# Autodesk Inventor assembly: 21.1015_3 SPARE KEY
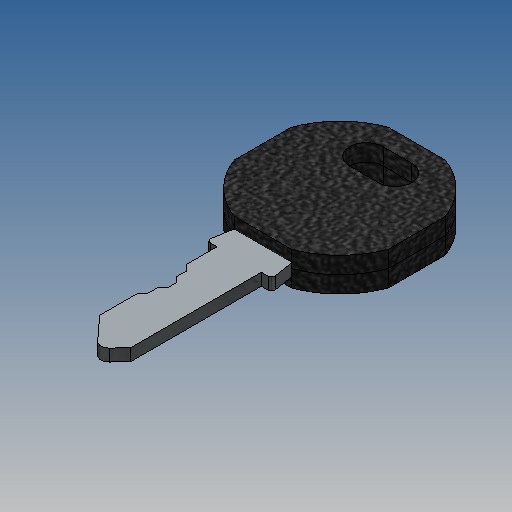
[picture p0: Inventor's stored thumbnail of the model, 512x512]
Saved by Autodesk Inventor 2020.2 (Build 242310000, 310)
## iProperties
Created: 2007-03
Part Number: 21.1015_3 SPARE KEY
Document SubType Name: Assembly
Designer: Andy Moles
Mass: 2.63365 g
Surface Area: 28.5344 cm^2
Volume: 2.50968 cm^3
Density: 1.0494 g/cm^3
Author: Andy Moles
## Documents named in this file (3)
- Y:\INVENTOR LIBRARIES\PARTS LIBRARY\HANDLES LOCKS STOPS\21.1015_3 SPARE KEY.iam
- Y:\INVENTOR LIBRARIES\PARTS LIBRARY\HANDLES LOCKS STOPS\SUBCOMPONENTS\EMKA SUBCOMPONENTS\1108-14-333_PRT.ipt
- Y:\INVENTOR LIBRARIES\PARTS LIBRARY\HANDLES LOCKS STOPS\SUBCOMPONENTS\EMKA SUBCOMPONENTS\1108-15-01_PRT.ipt
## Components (3 placed, 3 different names)
1. 1108-14-333
2. 1108-15-01 — Mate:1, Flush:1, Flush:2
3. 1108-15-01_PRT:2 — Mate:1, Flush:1, Flush:2
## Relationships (3: Flush 2, Mate 1)
- Mate:1: 1108-15-01 ↔ 1108-15-01_PRT:2
- Flush:1: 1108-15-01 ↔ 1108-15-01_PRT:2
- Flush:2: 1108-15-01 ↔ 1108-15-01_PRT:2
